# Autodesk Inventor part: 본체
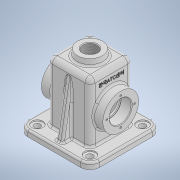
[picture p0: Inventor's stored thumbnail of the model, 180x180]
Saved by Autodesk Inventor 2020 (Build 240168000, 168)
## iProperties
Created: 2021-07
Part Number: 본체
Material: 일반
Document SubType Name: Modeling
Designer: Owner
Density: 1 g/cm^3
Appearance: 기본값
Mass: 278.253 g
Surface Area: 858.264 cm^2
Volume: 278.253 cm^3
Author: Owner
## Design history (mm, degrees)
sketch "스케치1"
  geometry: L1 (34, -34)-(-34, -34); L2 (-34, -34)-(-34, 34); L3 (-34, 34)-(34, 34); L4 (34, 34)-(34, -34); L5 (34, -34)-(-34, 34); L6 (-34, -34)-(34, 34); 1 further point
  constraints: 12 end point, 2 midpoint, 2 parallel, 1 horizontal, 1 perpendicular
  dimensions: "d0" = 68 distance of L2.end L3.end; "d1" = 68 distance of L1.end L2.end
extrude "돌출1" new body sketch "스케치1" distance "d2" = 105; taper "d3" = 0 deg
fillet "모깎기1" dims "d4" = 8
feature "쉘1" dims "d5" = 5
node "작업 평면1"
sketch "스케치2"
  geometry: C1 r 20 at (0, 0); 1 further point
  constraints: 1 centre point, 1 coincident
  dimensions: "d7" = 40 diameter of C1
extrude "돌출2" join sketch "스케치2" stored distance "d8" = 105; taper "d9" = 8 deg
sketch "스케치3"
  geometry: L1 (57, 57)-(-57, 57); L2 (-57, 57)-(-57, -57); L3 (-57, -57)-(57, -57); L4 (57, -57)-(57, 57); L5 (57, 57)-(-57, -57); L6 (-57, 57)-(57, -57); 1 further point
  constraints: 12 end point, 2 midpoint, 2 parallel, 1 horizontal, 1 perpendicular
  dimensions: "d10" = 114 distance of L3.end L2.end; "d11" = 114 distance of L1.end L2.end
extrude "돌출3" join sketch "스케치3" distance "d12" = 10; taper "d13" = 0 deg
fillet "모깎기2" dims "d14" = 15
sketch "스케치4"
  geometry: A1 r 15 centre (-42, -42) between (-57, -42) and (-42, -57) reference; 2 further points
  constraints: 1 coincident
hole "구멍1" sketch "스케치4" at (-42, -42) diameter "d15" = 10; stored, may be unused: countersink angle "d19" = 90 deg, drill point angle "d21" = 0 deg; dims "d16" = 8, "d17" = 18, "d18" = 2, "d20" = 20
fillet "모깎기3" dims "d25" = 8
sketch "스케치5"
  geometry: C1 r 20 at (0, 0) reference; 2 further points
  constraints: 1 coincident
hole "구멍2" sketch "스케치5" at (0, 0) diameter "d26" = 22.83494; stored, may be unused: countersink angle "d30" = 90 deg, drill point angle "d32" = 0 deg; dims "d27" = 50, "d28" = 18, "d29" = 2, "d31" = 59.3
node "작업 평면2"
sketch "스케치6"
  geometry: L1 (0, 42)-(0, -42) reference; C1 r 28.5 at (52, 0); 2 further points
  constraints: 1 centre point, 1 horizontal alignment, 1 midpoint
  dimensions: "d34" = 57 diameter of C1; "d35" = 52 distance from line of L1 C1.centre
extrude "돌출4" join sketch "스케치6" stored distance "d36" = 10; taper "d37" = 0 deg
sketch "스케치7"
  geometry: C1 r 28.5 at (0, 0) reference; 2 further points
  constraints: 1 coincident
hole "구멍3" sketch "스케치7" at (0, 0) diameter "d38" = 30; stored, may be unused: countersink angle "d42" = 82 deg, drill point angle "d44" = 0 deg; dims "d39" = 50, "d40" = 35, "d41" = 17, "d43" = 20
sketch "스케치8" dims "d45" = 44
  geometry: C1 r 28.5 at (0, 0) reference; 3 further points
  constraints: 2 vertical alignment, 1 coincident, 2 other
hole "구멍4" sketch "스케치8" at (0, 22) diameter "d46" = 3.242; stored, may be unused: countersink angle "d50" = 82 deg, drill point angle "d52" = 118 deg; dims "d47" = 8, "d48" = 35, "d49" = 17, "d51" = 10
sketch "스케치9"
  geometry: L1 (10, 57)-(10, 42) reference; L2 (10, 49)-(38.066, 44.051); L3 (10, 57)-(0, 57) reference; 1 further point
  constraints: 2 end point, 1 point on line
  dimensions: "d56" = 8 distance from line of L2.start L3; "d57" = 10 deg angle of L3 L2
feature "리브1" sketch "스케치9" dims "d58" = 1, "d59" = 10, "d60" = 0, "d61" = 0, "d62" = 1, "d63" = 1
sketch "스케치10"
  geometry: L1 (29, 29)-(-29, 29); L2 (-29, 29)-(-29, -29); L3 (-29, -29)-(29, -29); L4 (29, -29)-(29, 29); L5 (29, 29)-(-29, -29); L6 (-29, 29)-(29, -29); 1 further point
  constraints: 12 end point, 2 midpoint, 2 parallel, 1 horizontal, 1 perpendicular
  dimensions: "d64" = 58 distance of L3.end L2.end; "d65" = 58 distance of L2.end L1.end
extrude "돌출5" cut sketch "스케치10" distance "d66" = 51.5; taper "d67" = 0 deg
fillet "모깎기4" dims "d68" = 3
fillet "모깎기5" dims "d69" = 3
sketch "스케치11"
  geometry: L1 (6, 18)-(46, 18) reference; L2 (-16, -97)-(68, -97) reference; 3 further points
  constraints: 1 midpoint, 1 vertical alignment, 1 other
  dimensions: "d70" = 25 distance from line of L1 point (26, -7)
feature "엠보싱1" sketch "스케치11" dims "d71" = 0.5, "d72" = 0
fillet "모깎기6" dims "d73" = 3
fillet "모깎기7" dims "d74" = 3
chamfer "모따기1" distance "d75" = 1; stored, may be unused: second distance "d76" = 2, angle "d77" = 45 deg
chamfer "모따기2" distance "d78" = 1; stored, may be unused: second distance "d79" = 2, angle "d80" = 45 deg
fillet "모깎기8" dims "d81" = 3
fillet "모깎기10" dims "d83" = 3
fillet "모깎기11" dims "d84" = 3
fillet "모깎기12" dims "d85" = 0.3
fillet "모깎기13" dims "d86" = 0.3
node "솔리드1"
pattern_circular "원형 패턴1" dims angle "d23" = 360 deg
pattern_circular "원형 패턴2" dims angle "d54" = 360 deg
mirror "미러1"
mirror "미러2"
feature "A9D066F2-1C7D-4E18-AEED-F7BC21143FA4" dims "d15" = 10, "d16" = 8, "d17" = 18, "d18" = 2, "d19" = 90 deg, "d20" = 20, "d21" = 0
other parameters: "d6" = -115, "d33" = 49
